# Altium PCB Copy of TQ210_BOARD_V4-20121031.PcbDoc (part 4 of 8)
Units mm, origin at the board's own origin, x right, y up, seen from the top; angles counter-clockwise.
Board outline 191.2 x 131.27 mm, 2 copper layers (TopLayer, BottomLayer); 362 components, 455 nets, 1594 pads, 630 vias.
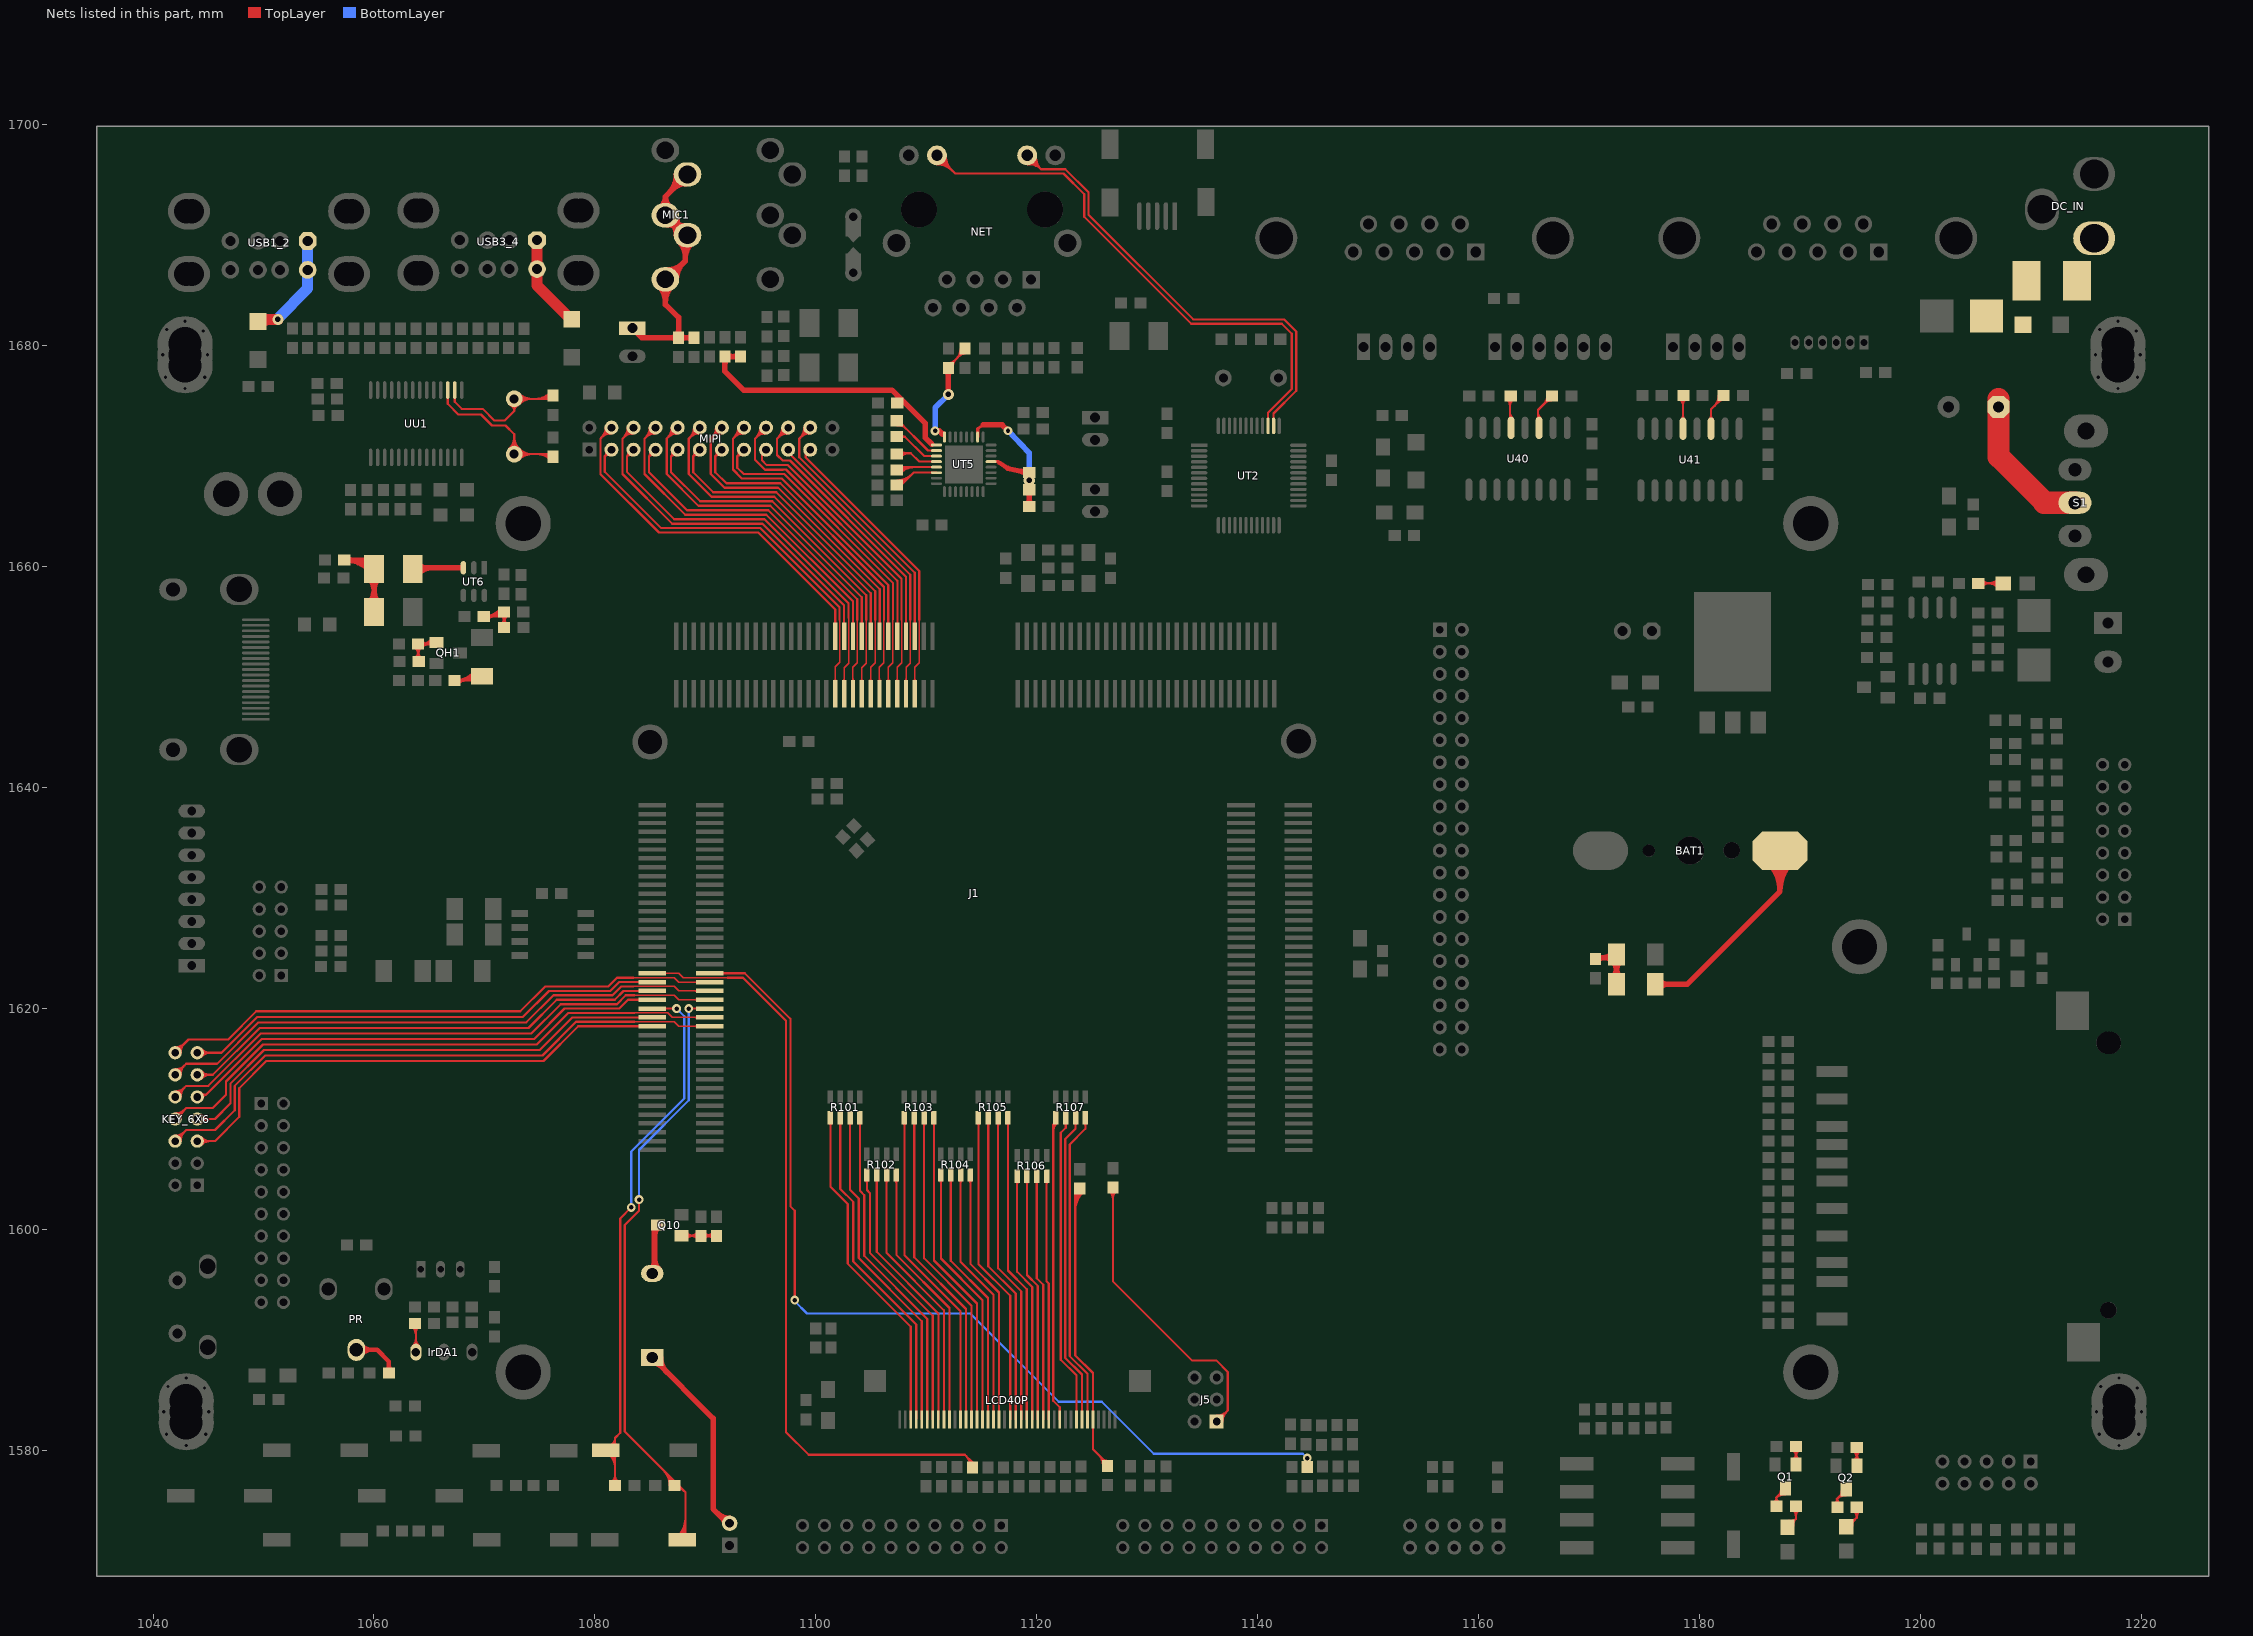
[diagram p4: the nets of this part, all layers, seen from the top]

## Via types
v1: diameter 1, hole 0.5, TopLayer to BottomLayer, 458 vias
v2: diameter 0.8, hole 0.4, TopLayer to BottomLayer, 172 vias

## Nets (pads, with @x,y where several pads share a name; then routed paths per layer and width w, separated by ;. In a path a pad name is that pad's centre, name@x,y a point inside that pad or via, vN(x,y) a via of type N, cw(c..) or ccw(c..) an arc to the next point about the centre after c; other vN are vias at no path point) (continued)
KP_COL2: J1.29 KEY_6X6.5 | length 50.1
  TopLayer w0.2: KEY_6X6.5@1044,1608 1045.6,1608 1047.8,1610.2 1047.8,1612.8 1050.25,1615.25 1075.35,1615.25 1078.5,1618.4 J1.29@1085.2,1618.4 ; KEY_6X6.5@1044.212,1607.788 cw(c1044.724,1607.276) 1044.724,1608 cw(c1044.724,1608.724) KEY_6X6.5@1044.212,1608.212 ; KEY_6X6.5@1044.354,1607.646 cw(c1045.207,1606.793) 1045.207,1608 cw(c1045.207,1609.207) KEY_6X6.5@1044.354,1608.354
KP_COL3: J1.30 KEY_6X6.6 | length 57.9
  TopLayer w0.135: 1083.6,1618.8 1087.2,1618.8 1087.6,1618.4 J1.30@1090.4,1618.4 ; J1.30@1089.256,1618.306 ccw(c1089.03,1618.08) 1089.03,1618.4 ccw(c1089.03,1618.72) J1.30@1089.256,1618.494
  TopLayer w0.2: KEY_6X6.6@1042,1608 1043,1609 1045.6,1609 1047.4,1610.8 1047.4,1613 1050.15,1615.75 1075.25,1615.75 1078.3,1618.8 1083.6,1618.8 ; KEY_6X6.6@1042,1608.3 ccw(c1042,1609.024) 1042.512,1608.512 ccw(c1043.024,1608) KEY_6X6.6@1042.3,1608 ; KEY_6X6.6@1042,1608.5 ccw(c1042,1609.707) 1042.854,1608.854 ccw(c1043.707,1608) KEY_6X6.6@1042.5,1608
KP_COL4: J1.31 KEY_6X6.7 | length 49.1
  TopLayer w0.2: KEY_6X6.7@1044,1610 1045.6,1610 1047,1611.4 1047,1613.2 1050.05,1616.25 1075,1616.25 1077.95,1619.2 J1.31@1085.2,1619.2 ; KEY_6X6.7@1044.212,1609.788 cw(c1044.724,1609.276) 1044.724,1610 cw(c1044.724,1610.724) KEY_6X6.7@1044.212,1610.212 ; KEY_6X6.7@1044.354,1609.646 cw(c1045.207,1608.793) 1045.207,1610 cw(c1045.207,1611.207) KEY_6X6.7@1044.354,1610.354
KP_COL5: J1.32 KEY_6X6.8 | length 56.8
  TopLayer w0.135: 1083.6,1619.6 1086.6,1619.6 1087,1619.2 J1.32@1090.4,1619.2 ; J1.32@1089.256,1619.106 ccw(c1089.03,1618.88) 1089.03,1619.2 ccw(c1089.03,1619.52) J1.32@1089.256,1619.294
  TopLayer w0.2: KEY_6X6.8@1042,1610 1043,1611 1045.4,1611 1046.6,1612.2 1046.6,1613.4 1049.95,1616.75 1074.75,1616.75 1077.6,1619.6 1083.6,1619.6 ; KEY_6X6.8@1042,1610.3 ccw(c1042,1611.024) 1042.512,1610.512 ccw(c1043.024,1610) KEY_6X6.8@1042.3,1610 ; KEY_6X6.8@1042,1610.5 ccw(c1042,1611.707) 1042.854,1610.854 ccw(c1043.707,1610) KEY_6X6.8@1042.5,1610
KP_COL6: J1.33 KEY7.1 R7.1 | length 55.3
  TopLayer w0.2: KEY7.1@1081.296,1579.646 cw(c1080.023,1578.373) 1081.824,1578.373 ; KEY7.1@1081.414,1580.441 ccw(c1081.05,1581.124) 1081.824,1581.124 ; KEY7.1@1081.438,1579.788 cw(c1080.506,1578.856) 1081.824,1578.856 ; KEY7.1@1081.509,1580.265 ccw(c1081.228,1580.79) 1081.824,1580.79 ; R7.1@1081.541,1577.107 ccw(c1080.858,1577.79) 1081.824,1577.79 ccw(c1082.79,1577.79) R7.1@1082.107,1577.107 ; KEY7.1@1081.579,1579.929 cw(c1080.988,1579.338) 1081.824,1579.338 ; R7.1@1081.824,1576.824 1081.824,1581.124 ; 1081.824,1579.213 cw(c1082.437,1579.213) KEY7.1@1082.004,1579.646 ; 1081.824,1580.787 ccw(c1082.437,1580.787) KEY7.1@1082.004,1580.354 ; v2(1083.3,1602) 1082.3,1601 1082.3,1581.6 1081.824,1581.124 ; J1.33@1085.21,1619.99 v2(1087.4,1620)
  BottomLayer w0.2: v2(1083.3,1602) 1083.3,1607.066 1088.1,1611.866 1088.1,1619.3 v2(1087.4,1620)
KP_COL7: J1.34 KEY8.1 R8.1 | length 63.4
  TopLayer w0.2: v2(1084,1602.7) 1084,1601.7 1082.7,1600.4 1082.7,1581.7 1088.2,1576.2 KEY8.1@1088.2,1571.9 ; 1086.207,1578.193 cw(c1084.838,1576.824) R8.1@1086.774,1576.824 ; 1086.548,1577.852 cw(c1085.521,1576.824) R8.1@1086.974,1576.824 ; 1086.89,1577.51 cw(c1086.204,1576.824) R8.1@1087.174,1576.824 ; R8.1@1087.274,1576.824 cw(c1087.328,1576.233) R8.1@1087.747,1576.653 ; R8.1@1087.292,1576.625 cw(c1087.378,1575.68) 1088.049,1576.351 ; KEY8.1@1087.546,1572.254 ccw(c1085.969,1573.831) 1088.2,1573.831 ; KEY8.1@1087.688,1572.112 ccw(c1086.451,1573.349) 1088.2,1573.349 ; KEY8.1@1087.829,1571.971 ccw(c1086.934,1572.866) 1088.2,1572.866 ; v2(1088.5,1620) J1.34@1090.41,1619.99
  BottomLayer w0.2: v2@1084,1602.9 1084,1607.2 1088.5,1611.7 v2(1088.5,1620)
KP_ROW0: J1.35 KEY_6X6.9 | length 46.3
  TopLayer w0.2: KEY_6X6.9@1043.8,1612 KEY_6X6.9@1044,1612 1044.2,1612.2 1044.8,1612.2 ; KEY_6X6.9@1044.297,1611.96 cw(c1044.571,1611.923) 1044.571,1612.2 ; KEY_6X6.9@1044.354,1612.354 ccw(c1044.724,1612.724) 1044.724,1612.2 ; KEY_6X6.9@1044.496,1611.934 cw(c1044.8,1611.893) 1044.8,1612.2 ; J1.35@1085.2,1620.8 1083.004,1620.8 1082.204,1620 1077.25,1620 1074.5,1617.25 1049.85,1617.25 1044.8,1612.2
KP_ROW1: J1.36 KEY_6X6.10 | length 55.9
  TopLayer w0.135: 1083.6,1621.2 1087.2,1621.2 1087.6,1620.8 J1.36@1090.4,1620.8 ; J1.36@1089.256,1620.706 ccw(c1089.03,1620.48) 1089.03,1620.8 ccw(c1089.03,1621.12) J1.36@1089.256,1620.894
  TopLayer w0.2: KEY_6X6.10@1042,1612 1043,1613 1045,1613 1049.75,1617.75 1074.25,1617.75 1076.9,1620.4 1082,1620.4 1082.8,1621.2 1083.6,1621.2 ; KEY_6X6.10@1042,1612.3 ccw(c1042,1613.024) 1042.512,1612.512 ccw(c1043.024,1612) KEY_6X6.10@1042.3,1612 ; KEY_6X6.10@1042,1612.5 ccw(c1042,1613.707) 1042.854,1612.854 ccw(c1043.707,1612) KEY_6X6.10@1042.5,1612
KP_ROW2: J1.37 KEY_6X6.11 | length 47.4
  TopLayer w0.2: KEY_6X6.11@1044,1614 1045.4,1614 1049.65,1618.25 1074,1618.25 1076.55,1620.8 1081.8,1620.8 1082.6,1621.6 J1.37@1085.2,1621.6 ; KEY_6X6.11@1044.212,1613.788 cw(c1044.724,1613.276) 1044.724,1614 cw(c1044.724,1614.724) KEY_6X6.11@1044.212,1614.212 ; KEY_6X6.11@1044.354,1613.646 cw(c1045.207,1612.793) 1045.207,1614 cw(c1045.207,1615.207) KEY_6X6.11@1044.354,1614.354
KP_ROW3: J1.38 KEY_6X6.12 | length 55.4
  TopLayer w0.135: 1083.5,1622 1087.2,1622 1087.6,1621.6 J1.38@1090.4,1621.6 ; J1.38@1089.256,1621.506 ccw(c1089.03,1621.28) 1089.03,1621.6 ccw(c1089.03,1621.92) J1.38@1089.256,1621.694
  TopLayer w0.2: KEY_6X6.12@1042,1614 1043,1615 1045.8,1615 1049.55,1618.75 1073.8,1618.75 1076.25,1621.2 1081.6,1621.2 1082.4,1622 1083.5,1622 ; KEY_6X6.12@1042,1614.3 ccw(c1042,1615.024) 1042.512,1614.512 ccw(c1043.024,1614) KEY_6X6.12@1042.3,1614 ; KEY_6X6.12@1042,1614.5 ccw(c1042,1615.707) 1042.854,1614.854 ccw(c1043.707,1614) KEY_6X6.12@1042.5,1614
KP_ROW4: J1.39 KEY_6X6.13 | length 46.9
  TopLayer w0.2: KEY_6X6.13@1044,1616 1046.2,1616 1049.45,1619.25 1073.5,1619.25 1075.85,1621.6 1081.4,1621.6 1082.2,1622.4 J1.39@1085.2,1622.4 ; KEY_6X6.13@1044.212,1615.788 cw(c1044.724,1615.276) 1044.724,1616 cw(c1044.724,1616.724) KEY_6X6.13@1044.212,1616.212 ; KEY_6X6.13@1044.354,1615.646 cw(c1045.207,1614.793) 1045.207,1616 cw(c1045.207,1617.207) KEY_6X6.13@1044.354,1616.354
KP_ROW5: J1.40 KEY_6X6.14 | length 54.4
  TopLayer w0.135: 1083.5,1622.8 1087.2,1622.8 1087.6,1622.4 J1.40@1090.4,1622.4
  TopLayer w0.2: KEY_6X6.14@1042,1616 1043.2,1617.2 1046.8,1617.2 1049.35,1619.75 1073.25,1619.75 1075.5,1622 1081.2,1622 1082,1622.8 1083.5,1622.8 ; KEY_6X6.14@1042,1616.3 ccw(c1042,1617.024) 1042.512,1616.512 ccw(c1043.024,1616) KEY_6X6.14@1042.3,1616 ; KEY_6X6.14@1042,1616.5 ccw(c1042,1617.707) 1042.854,1616.854 ccw(c1043.707,1616) KEY_6X6.14@1042.5,1616
KP_ROW6: J1.41 RM22.1 | length 71.4
  TopLayer w0.135: J1.41@1085.2,1623.2 1087.6,1623.2 1088,1622.8 1092,1622.8
  TopLayer w0.2: 1092,1622.8 1093.406,1622.8 1097.3,1618.906 1097.3,1581.654 1099.354,1579.6 1113.5,1579.6 1114.2,1578.9 RM22.1@1114.2,1578.448 ; 1113.621,1579.479 cw(c1112.704,1578.561) RM22.1@1114,1578.507 ; 1113.943,1579.157 cw(c1113.322,1578.535) RM22.1@1114.2,1578.498
KP_ROW7: J1.42 RMB22.1 | length 87
  TopLayer w0.2: J1.42@1090.41,1623.19 1090.421,1623.2 1093.572,1623.2 1097.7,1619.072 1097.7,1602.1 1098.1,1601.7 v2(1098.1,1593.6)
  BottomLayer w0.2: v2(1098.1,1593.6) 1098.1,1593.5 1099.2,1592.4 1114,1592.4 1122,1584.4 1125.9,1584.4 1130.6,1579.7 1144.1,1579.7 v2(1144.5,1579.3)
LAN2_LNK: NET.10 UT2.38 | length 46.2
  TopLayer w0.2: NET.10@1119.14,1697.25 1120.39,1696 ; NET.10@1119.179,1696.651 cw(c1119.254,1695.489) 1120.077,1696.313 cw(c1120.901,1697.136) NET.10@1119.739,1697.211 ; NET.10@1119.192,1696.452 cw(c1119.292,1694.902) 1120.39,1696 ; NET.10@1119.938,1697.198 ccw(c1121.488,1697.098) 1120.39,1696 ; UT2.38@1141.453,1672.754 1141.453,1673.888 1143.5,1675.934 1143.5,1681.3 1142.4,1682.4 1134.166,1682.4 1124.7,1691.866 1124.7,1693.9 1122.6,1696 1120.39,1696
LAN2_SPD: NET.11 UT2.39 | length 56.1
  TopLayer w0.2: NET.11@1110.97,1696.45 cw(c1110.97,1694.519) 1112.336,1695.884 cw(c1113.701,1697.25) NET.11@1111.77,1697.25 ; NET.11@1110.97,1696.65 cw(c1110.97,1695.201) 1111.994,1696.226 cw(c1113.019,1697.25) NET.11@1111.57,1697.25 ; NET.11@1110.97,1696.85 cw(c1110.97,1695.884) 1111.653,1696.567 cw(c1112.336,1697.25) NET.11@1111.37,1697.25 ; NET.11@1110.97,1697.25 1112.62,1695.6 1122.434,1695.6 1124.3,1693.734 1124.3,1691.7 1134,1682 1142.2,1682 1143.1,1681.1 1143.1,1676.1 1140.953,1673.953 UT2.39@1140.953,1672.754
LHSYNC: LCD40P.35 R107.8 | length 29.2
  TopLayer w0.2: R107.8@1124.305,1609.67 cw(c1124.049,1609.414) 1124.411,1609.414 cw(c1124.773,1609.414) R107.8@1124.517,1609.67 ; R107.8@1124.411,1610.126 1124.411,1609.111 1122.998,1607.698 1122.998,1588.534 1124.6,1586.931 LCD40P.35@1124.6,1582.7
LVCLK: CL5.1 LCD40P.36 R108.1 | length 34.2
  TopLayer w0.2: 1123.498,1601.713 cw(c1125.837,1601.713) R108.1@1124.183,1603.367 ; 1123.498,1602.196 cw(c1125.354,1602.196) R108.1@1124.041,1603.509 ; 1123.498,1602.679 cw(c1124.871,1602.679) R108.1@1123.9,1603.65 ; R108.1@1123.498,1603.162 cw(c1124.388,1603.162) R108.1@1123.759,1603.791 ; R108.1@1124.1,1604 1123.498,1603.398 1123.498,1588.599 1125.1,1586.997 LCD40P.36@1125.1,1582.8 1125.1,1580.1 CL5.1@1126.6,1578.6 ; 1125.611,1579.589 cw(c1124.672,1578.65) CL5.1@1126,1578.65 ; 1125.953,1579.247 cw(c1125.355,1578.65) CL5.1@1126.2,1578.65 ; 1125.973,1579.227 ccw(c1126.4,1579.654) CL5.1@1126.4,1579.05
LVD0: LCD40P.3 R101.5 | length 30.9
  TopLayer w0.2: R101.5@1101.227,1609.67 cw(c1100.971,1609.414) 1101.333,1609.414 cw(c1101.695,1609.414) R101.5@1101.439,1609.67 ; R101.5@1101.333,1610.126 1101.333,1603.857 1102.89,1602.3 1102.89,1596.91 1108.6,1591.2 LCD40P.3@1108.6,1582.8
LVD1: LCD40P.4 R101.6 | length 30.6
  TopLayer w0.2: R101.6@1102.116,1609.67 cw(c1101.86,1609.414) 1102.222,1609.414 cw(c1102.584,1609.414) R101.6@1102.328,1609.67 ; R101.6@1102.222,1610.126 1102.222,1603.668 1103.39,1602.5 1103.39,1597.11 1109.1,1591.4 LCD40P.4@1109.1,1582.9
LVD2: LCD40P.5 R101.7 | length 30.7
  TopLayer w0.2: R101.7@1103.005,1609.67 cw(c1102.775,1609.44) 1103.1,1609.44 ; 1103.1,1609.387 cw(c1103.5,1609.387) R101.7@1103.217,1609.67 ; R101.7@1103.1,1610.2 1103.1,1603.59 1103.89,1602.8 1103.89,1597.41 1109.6,1591.7 LCD40P.5@1109.6,1582.8
LVD3: LCD40P.6 R101.8 | length 30.4
  TopLayer w0.2: R101.8@1103.894,1609.67 cw(c1103.638,1609.414) 1104,1609.414 cw(c1104.362,1609.414) R101.8@1104.106,1609.67 ; R101.8@1104,1610.126 1104,1603.5 1104.39,1603.11 1104.39,1597.61 1110.1,1591.9 LCD40P.6@1110.1,1582.8
LVD4: LCD40P.7 R102.5 | length 25.2
  TopLayer w0.2: R102.5@1104.527,1604.47 cw(c1104.271,1604.214) 1104.633,1604.214 cw(c1104.995,1604.214) R102.5@1104.739,1604.47 ; R102.5@1104.633,1604.926 1104.633,1603.567 1104.9,1603.3 1104.9,1597.9 1110.6,1592.2 LCD40P.7@1110.6,1582.8
LVD5: LCD40P.8 R102.6 | length 25
  TopLayer w0.2: R102.6@1105.416,1604.47 cw(c1105.16,1604.214) 1105.522,1604.214 cw(c1105.884,1604.214) R102.6@1105.628,1604.47 ; R102.6@1105.522,1604.926 1105.522,1597.978 1111.1,1592.4 LCD40P.8@1111.1,1582.8
LVD6: LCD40P.9 R102.7 | length 24.9
  TopLayer w0.2: R102.7@1106.305,1604.47 cw(c1106.049,1604.214) 1106.411,1604.214 cw(c1106.773,1604.214) R102.7@1106.517,1604.47 ; R102.7@1106.411,1604.926 1106.411,1597.889 1111.6,1592.7 LCD40P.9@1111.6,1582.7
LVD7: LCD40P.10 R102.8 | length 24.7
  TopLayer w0.2: R102.8@1107.194,1604.47 cw(c1106.938,1604.214) 1107.3,1604.214 cw(c1107.662,1604.214) R102.8@1107.406,1604.47 ; R102.8@1107.3,1604.926 1107.3,1597.7 1112.1,1592.9 LCD40P.10@1112.1,1582.8
LVD8: LCD40P.12 R103.5 | length 30.1
  TopLayer w0.2: R103.5@1107.927,1609.67 cw(c1107.671,1609.414) 1108.033,1609.414 cw(c1108.395,1609.414) R103.5@1108.139,1609.67 ; R103.5@1108.033,1610.126 1108.033,1597.667 1113.1,1592.6 LCD40P.12@1113.1,1582.7
LVD9: LCD40P.13 R103.6 | length 29.8
  TopLayer w0.2: R103.6@1108.816,1609.67 cw(c1108.56,1609.414) 1108.922,1609.414 cw(c1109.284,1609.414) R103.6@1109.028,1609.67 ; R103.6@1108.922,1610.126 1108.922,1597.478 1113.6,1592.8 LCD40P.13@1113.6,1582.8
LVD10: LCD40P.14 R103.7 | length 29.7
  TopLayer w0.2: R103.7@1109.705,1609.67 cw(c1109.449,1609.414) 1109.811,1609.414 cw(c1110.173,1609.414) R103.7@1109.917,1609.67 ; R103.7@1109.811,1610.126 1109.811,1597.389 1114.1,1593.1 LCD40P.14@1114.1,1582.8
LVD11: LCD40P.15 R103.8 | length 29.5
  TopLayer w0.2: R103.8@1110.594,1609.67 cw(c1110.338,1609.414) 1110.7,1609.414 cw(c1111.062,1609.414) R103.8@1110.806,1609.67 ; R103.8@1110.7,1610.126 1110.7,1597.2 1114.6,1593.3 LCD40P.15@1114.6,1582.8
LVD12: LCD40P.16 R104.5 | length 24.3
  TopLayer w0.2: R104.5@1111.227,1604.47 cw(c1110.971,1604.214) 1111.333,1604.214 cw(c1111.695,1604.214) R104.5@1111.439,1604.47 ; R104.5@1111.333,1604.926 1111.333,1597.367 1115.1,1593.6 LCD40P.16@1115.1,1582.8
LVD13: LCD40P.17 R104.6 | length 24
  TopLayer w0.2: R104.6@1112.116,1604.47 cw(c1111.86,1604.214) 1112.222,1604.214 cw(c1112.584,1604.214) R104.6@1112.328,1604.47 ; R104.6@1112.222,1604.926 1112.222,1597.178 1115.6,1593.8 LCD40P.17@1115.6,1582.9
LVD14: LCD40P.18 R104.7 | length 23.8
  TopLayer w0.2: R104.7@1113.005,1604.47 cw(c1112.749,1604.214) 1113.111,1604.214 cw(c1113.473,1604.214) R104.7@1113.217,1604.47 ; R104.7@1113.111,1604.926 1113.111,1597.089 1116.1,1594.1 LCD40P.18@1116.1,1582.9
LVD15: LCD40P.19 R104.8 | length 23.8
  TopLayer w0.2: R104.8@1113.894,1604.47 cw(c1113.638,1604.214) 1114,1604.214 cw(c1114.362,1604.214) R104.8@1114.106,1604.47 ; R104.8@1114,1604.926 1114,1596.9 1116.6,1594.3 LCD40P.19@1116.6,1582.8
LVD16: LCD40P.21 R105.5 | length 29.1
  TopLayer w0.2: R105.5@1114.627,1609.67 cw(c1114.371,1609.414) 1114.733,1609.414 cw(c1115.095,1609.414) R105.5@1114.839,1609.67 ; R105.5@1114.733,1610.126 1114.733,1596.862 1117.6,1593.995 LCD40P.21@1117.6,1582.8
LVD17: LCD40P.22 R105.6 | length 28.9
  TopLayer w0.2: R105.6@1115.516,1609.67 cw(c1115.26,1609.414) 1115.622,1609.414 cw(c1115.984,1609.414) R105.6@1115.728,1609.67 ; R105.6@1115.622,1610.126 1115.622,1596.673 1118.1,1594.195 LCD40P.22@1118.1,1582.8
LVD18: LCD40P.23 R105.7 | length 28.8
  TopLayer w0.2: R105.7@1116.405,1609.67 cw(c1116.149,1609.414) 1116.511,1609.414 cw(c1116.873,1609.414) R105.7@1116.617,1609.67 ; R105.7@1116.511,1610.126 1116.511,1596.484 1118.6,1594.395 LCD40P.23@1118.6,1582.8
LVD19: LCD40P.24 R105.8 | length 28.6
  TopLayer w0.2: R105.8@1117.294,1609.67 cw(c1117.038,1609.414) 1117.4,1609.414 cw(c1117.762,1609.414) R105.8@1117.506,1609.67 ; R105.8@1117.4,1610.126 1117.4,1596.295 1119.1,1594.595 LCD40P.24@1119.1,1582.8
LVD20: LCD40P.25 R106.5 | length 23.2
  TopLayer w0.2: R106.5@1118.127,1604.37 cw(c1117.871,1604.114) 1118.233,1604.114 cw(c1118.595,1604.114) R106.5@1118.339,1604.37 ; R106.5@1118.233,1604.826 1118.233,1596.162 1119.6,1594.795 LCD40P.25@1119.6,1582.8
LVD21: LCD40P.26 R106.6 | length 23
  TopLayer w0.2: R106.6@1119.016,1604.37 cw(c1118.76,1604.114) 1119.122,1604.114 cw(c1119.484,1604.114) R106.6@1119.228,1604.37 ; R106.6@1119.122,1604.826 1119.122,1595.873 1120.1,1594.895 LCD40P.26@1120.1,1582.8
LVD22: LCD40P.27 R106.7 | length 22.8
  TopLayer w0.2: R106.7@1119.905,1604.37 cw(c1119.649,1604.114) 1120.011,1604.114 cw(c1120.373,1604.114) R106.7@1120.117,1604.37 ; R106.7@1120.011,1604.826 1120.011,1595.589 1120.6,1595 LCD40P.27@1120.6,1582.8
LVD23: LCD40P.28 R106.8 | length 22.7
  TopLayer w0.2: R106.8@1120.794,1604.37 cw(c1120.538,1604.114) 1120.9,1604.114 cw(c1121.262,1604.114) R106.8@1121.006,1604.37 ; R106.8@1120.9,1604.826 1120.9,1595.3 1121.1,1595.1 LCD40P.28@1121.1,1582.8
LVDEN: LCD40P.33 R107.6 | length 28.8
  TopLayer w0.2: R107.6@1122.527,1609.67 cw(c1122.271,1609.414) 1122.633,1609.414 cw(c1122.995,1609.414) R107.6@1122.739,1609.67 ; R107.6@1122.633,1610.126 1122.633,1609.2 1122.19,1608.757 1122.19,1588.21 1123.6,1586.8 LCD40P.33@1123.6,1582.7
LVSYNC: LCD40P.34 R107.7 | length 28.9
  TopLayer w0.2: R107.7@1123.416,1609.67 cw(c1123.16,1609.414) 1123.522,1609.414 cw(c1123.884,1609.414) R107.7@1123.628,1609.67 ; R107.7@1123.522,1610.126 1123.522,1609.122 1122.598,1608.198 1122.598,1588.368 1124.1,1586.866 LCD40P.34@1124.1,1582.8
LXPWMTOUT0: LCD40P.30 R107.5 | length 29.7
  TopLayer w0.2: 1121.5,1608.825 cw(c1122.695,1608.825) R107.5@1121.85,1609.67 ; 1121.5,1609.308 cw(c1122.212,1609.308) R107.5@1121.709,1609.811 ; 1121.516,1609.516 ccw(c1121.317,1609.715) R107.5@1121.596,1609.755 ; R107.5@1121.543,1609.543 cw(c1121.744,1609.341) R107.5@1121.744,1609.626 ; R107.5@1121.744,1610.126 1121.744,1609.744 1121.5,1609.5 1121.5,1584.5 1122.1,1583.9 LCD40P.30@1122.1,1582.8
LXPWMTOUT3: J5.1 R109.1 | length 35.3
  TopLayer w0.2: R109.1@1126.617,1603.467 cw(c1125.934,1602.784) 1126.9,1602.784 cw(c1127.866,1602.784) R109.1@1127.183,1603.467 ; R109.1@1126.9,1603.8 1126.9,1595.3 1134.052,1588.148 1136.252,1588.148 1137.3,1587.1 1137.3,1583.6 J5.1@1136.3,1582.6 ; J5.1@1136.872,1583.172 cw(c1136.3,1583.744) 1136.3,1582.935 ccw(c1136.3,1583.744) J5.1@1136.872,1583.172 ; J5.1@1136.872,1583.172 ccw(c1137.444,1582.6) 1136.635,1582.6 cw(c1137.444,1582.6) J5.1@1136.872,1583.172 ; 1137.213,1583.513 cw(c1136.3,1584.427) 1136.3,1583.135 ccw(c1136.3,1584.427) 1137.213,1583.513 ; 1137.213,1583.513 ccw(c1138.127,1582.6) 1136.835,1582.6 cw(c1138.127,1582.6) 1137.213,1583.513
MIC: C524.1 UT5.4 | length 6
  TopLayer w0.2: C524.1@1107.329,1670.278 1108.603,1670.278 1109.357,1669.524 UT5.4@1110.928,1669.524 ; C524.1@1107.519,1670.083 cw(c1107.992,1669.61) 1107.992,1670.278 ; C524.1@1107.661,1669.941 cw(c1108.475,1669.127) 1108.475,1670.278 ; C524.1@1107.661,1670.507 ccw(c1108.212,1671.058) 1108.212,1670.278
MIC1_P1: C525.1 MIC1.2 MIC1.3 MIC1.10 MIC1.11 MIC2.1 R505.1 | length 51.5
  TopLayer w0.5: MIC2.1@1083.4,1681.6 1084.264,1680.736 1088.979,1680.736 R505.1@1088.981,1680.733 ; MIC1.10@1085.784,1685.424 cw(c1084.333,1683.973) 1086.385,1683.973 cw(c1088.437,1683.973) MIC1.10@1086.986,1685.424 ; MIC1.11@1085.875,1692.505 ccw(c1085.11,1693.525) 1086.385,1693.525 ; MIC1.10@1086.285,1685.775 1088.185,1687.675 MIC1.3@1088.185,1690.025 ; 1086.385,1683.707 MIC1.10@1086.385,1686.025 ; 1086.385,1683.766 1087.574,1682.577 C525.1@1087.574,1680.736 ; MIC1.10@1086.535,1686.875 ccw(c1086.535,1688.927) 1087.986,1687.476 ccw(c1089.437,1686.025) MIC1.10@1087.385,1686.025 ; MIC1.11@1086.535,1690.975 cw(c1086.535,1689.285) MIC1.3@1087.73,1690.48 ; 1086.678,1693.818 ccw(c1084.971,1695.525) MIC1.2@1087.385,1695.525 ; MIC1.11@1086.699,1691.511 ccw(c1088.235,1693.047) MIC1.3@1088.235,1690.875 ; MIC1.11@1086.82,1691.39 cw(c1085.454,1690.025) MIC1.3@1087.385,1690.025 ; MIC1.11@1086.885,1691.825 ccw(c1088.092,1691.825) 1087.239,1690.971 ; MIC1.11@1086.895,1692.505 cw(c1087.66,1693.525) 1086.385,1693.525 ; 1087.04,1694.18 cw(c1088.235,1692.985) MIC1.2@1088.235,1694.675 ; MIC1.11@1087.385,1691.825 ccw(c1089.799,1691.825) MIC1.3@1088.092,1690.118 ; C525.1@1087.397,1680.559 ccw(c1086.97,1680.132) 1086.97,1680.736 ccw(c1086.97,1681.339) C525.1@1087.397,1680.912 ; C525.1@1087.397,1680.962 ccw(c1086.97,1681.389) 1087.574,1681.389 ccw(c1088.178,1681.389) C525.1@1087.751,1680.962 ; 1087.532,1694.671 ccw(c1086.678,1695.525) MIC1.2@1087.885,1695.525 ; MIC1.3@1087.634,1689.424 cw(c1086.304,1688.093) 1088.185,1688.093 ; C525.1@1087.751,1680.559 cw(c1088.178,1680.132) 1088.178,1680.736 cw(c1088.178,1681.339) C525.1@1087.751,1680.912 ; 1088.185,1687.852 cw(c1090.408,1687.852) MIC1.3@1088.836,1689.424 ; 1088.372,1680.736 cw(c1088.372,1680.125) R505.1@1088.804,1680.557 ; 1088.383,1680.736 ccw(c1088.383,1681.332) R505.1@1088.804,1680.91 ; MIC1.3@1088.385,1690.025 MIC1.3@1088.185,1690.025 ; MIC1.2@1088.385,1695.525 1086.385,1693.525 ; R505.1@1088.97,1680.83 R505.1@1089,1680.8 ; 1086.385,1693.525 MIC1.11@1086.385,1691.825 MIC1.3@1088.185,1690.025
MICBIAS: C509.1 C511.1 R504.2 UT5.1 | length 29.5
  TopLayer w0.5: C509.1@1091.604,1678.807 cw(c1091.177,1678.38) 1091.781,1678.38 cw(c1092.385,1678.38) C509.1@1091.958,1678.807 ; C509.1@1091.958,1678.857 cw(c1092.385,1678.43) 1092.385,1679.033 cw(c1092.385,1679.637) C509.1@1091.958,1679.21 ; C511.1@1093.004,1678.857 ccw(c1092.577,1678.43) 1092.577,1679.033 ccw(c1092.577,1679.637) C511.1@1093.004,1679.21 ; C511.1@1093.181,1679.033 C509.1@1091.781,1679.033 1091.781,1677.683 1093.464,1676 1106.9,1676 1109.9,1673 1109.9,1671.7 UT5.1@1110.501,1671.099 ; 1107.281,1675.619 cw(c1106.556,1674.894) R504.2@1107.577,1674.801 ; R504.2@1107.428,1675.074 cw(c1107.428,1674.113) 1108.108,1674.792
MIPI_MD_DN0: J1.128 MIPI.13 | length 33.3
  TopLayer w0.135: J1.128@1105.677,1649.649 ccw(c1105.451,1649.876) 1105.771,1649.876 ccw(c1106.09,1649.876) J1.128@1105.864,1649.649 ; J1.128@1105.771,1648.506 1105.771,1650.905 1106.17,1651.305 1106.17,1655.394
  TopLayer w0.2: MIPI.13@1090.996,1670.422 cw(c1090.613,1670.287) 1090.9,1670 ; MIPI.13@1091.322,1670.096 ccw(c1091.187,1669.713) 1090.9,1670 ; MIPI.13@1091.5,1670.6 1090.9,1670 ; 1106.17,1655.191 1106.17,1658.163 1096.778,1667.554 1091.911,1667.554 1090.9,1668.566 1090.9,1670
MIPI_MD_DN1: J1.130 MIPI.15 | length 32.1
  TopLayer w0.135: J1.130@1106.477,1649.649 ccw(c1106.251,1649.876) 1106.571,1649.876 ccw(c1106.89,1649.876) J1.130@1106.664,1649.649 ; J1.130@1106.571,1648.506 1106.571,1650.893 1106.983,1651.305 1106.983,1655.394
  TopLayer w0.2: MIPI.15@1092.996,1670.422 cw(c1092.613,1670.287) 1092.9,1670 ; MIPI.15@1093.322,1670.096 ccw(c1093.187,1669.713) 1092.9,1670 ; MIPI.15@1093.5,1670.6 1092.9,1670 ; 1106.983,1655.216 1106.983,1658.544 1097.134,1668.393 1093.473,1668.393 1092.9,1668.966 1092.9,1670
MIPI_MD_DN2: J1.132 MIPI.17 | length 29.5
  TopLayer w0.135: J1.132@1107.277,1649.649 ccw(c1107.051,1649.876) 1107.371,1649.876 ccw(c1107.69,1649.876) J1.132@1107.464,1649.649 ; J1.132@1107.371,1648.506 1107.371,1650.905 1107.77,1651.305 1107.77,1655.394
  TopLayer w0.2: MIPI.17@1095.5,1670.6 1095.132,1670.232 1095.132,1669.633 1095.56,1669.205 1097.49,1669.205 1107.77,1658.925 1107.77,1655.191
MIPI_MD_DN3: J1.134 MIPI.19 | length 27.2
  TopLayer w0.135: J1.134@1108.077,1649.649 ccw(c1107.851,1649.876) 1108.171,1649.876 ccw(c1108.49,1649.876) J1.134@1108.264,1649.649 ; J1.134@1108.171,1648.506 1108.171,1650.892 1108.558,1651.279 1108.558,1655.394
  TopLayer w0.2: MIPI.19@1097.585,1670.253 1097.592,1670.253 1108.558,1659.287 1108.558,1655.191
MIPI_MD_DP0: J1.127 MIPI.14 | length 31.8
  TopLayer w0.2: MIPI.14@1090.965,1672.6 cw(c1089.673,1672.6) 1090.587,1671.687 cw(c1091.5,1670.773) MIPI.14@1091.5,1672.065 ; MIPI.14@1091.165,1672.6 cw(c1090.356,1672.6) 1090.928,1672.028 cw(c1091.5,1671.456) MIPI.14@1091.5,1672.265 ; MIPI.14@1091.5,1672.6 1090.5,1671.6 1090.5,1668.4 1091.746,1667.154 1096.594,1667.154 1105.789,1657.96 1105.789,1653.724 J1.127@1105.771,1653.706
MIPI_MD_DP1: J1.129 MIPI.16 | length 30.6
  TopLayer w0.2: MIPI.16@1092.965,1672.6 cw(c1091.673,1672.6) 1092.587,1671.687 cw(c1093.5,1670.773) MIPI.16@1093.5,1672.065 ; MIPI.16@1093.165,1672.6 cw(c1092.356,1672.6) 1092.928,1672.028 cw(c1093.5,1671.456) MIPI.16@1093.5,1672.265 ; MIPI.16@1093.5,1672.6 1092.5,1671.6 1092.5,1668.8 1093.307,1667.993 1096.924,1667.993 1106.571,1658.346 J1.129@1106.571,1653.706
MIPI_MD_DP2: J1.131 MIPI.18 | length 30.1
  TopLayer w0.2: MIPI.18@1094.965,1672.6 cw(c1093.673,1672.6) 1094.587,1671.687 cw(c1095.5,1670.773) MIPI.18@1095.5,1672.065 ; MIPI.18@1095.165,1672.6 cw(c1094.356,1672.6) 1094.928,1672.028 cw(c1095.5,1671.456) MIPI.18@1095.5,1672.265 ; MIPI.18@1095.5,1672.6 1094.5,1671.6 1094.5,1669.7 1095.407,1668.793 1097.007,1668.793 ; 1095.985,1668.805 1097.305,1668.805 1107.37,1658.741 ; J1.131@1107.371,1653.706 1107.389,1653.724 1107.389,1658.722
MIPI_MD_DP3: J1.133 MIPI.20 | length 27.8
  TopLayer w0.2: MIPI.20@1096.965,1672.6 cw(c1095.673,1672.6) 1096.587,1671.687 cw(c1097.5,1670.773) MIPI.20@1097.5,1672.065 ; MIPI.20@1097.165,1672.6 cw(c1096.356,1672.6) 1096.928,1672.028 cw(c1097.5,1671.456) MIPI.20@1097.5,1672.265 ; MIPI.20@1097.5,1672.6 1096.5,1671.6 1096.5,1670.118 1097,1669.618 1097.661,1669.618 1108.171,1659.109 J1.133@1108.171,1653.706
MIPI_MD_NCLK: J1.136 MIPI.21 | length 27.4
  TopLayer w0.135: J1.136@1108.877,1649.649 ccw(c1108.651,1649.876) 1108.971,1649.876 ccw(c1109.29,1649.876) J1.136@1109.064,1649.649 ; J1.136@1108.971,1648.506 1108.971,1650.905 1109.37,1651.305 1109.37,1655.394
  TopLayer w0.2: MIPI.21@1099.5,1670.6 1099.094,1670.194 1099.094,1669.894 1109.37,1659.617 1109.37,1655.191
MIPI_MD_PCLK: J1.135 MIPI.22 | length 26.9
  TopLayer w0.2: MIPI.22@1098.965,1672.6 cw(c1097.673,1672.6) 1098.587,1671.687 cw(c1099.5,1670.773) MIPI.22@1099.5,1672.065 ; MIPI.22@1099.165,1672.6 cw(c1098.356,1672.6) 1098.928,1672.028 cw(c1099.5,1671.456) MIPI.22@1099.5,1672.265 ; MIPI.22@1099.5,1672.6 1098.5,1671.6 1098.5,1669.922 1108.971,1659.452 J1.135@1108.971,1653.706
MIPI_SD_DN0: J1.118 MIPI.3 | length 38.2
  TopLayer w0.135: J1.118@1101.671,1649.641 ccw(c1101.445,1649.867) 1101.765,1649.867 ccw(c1102.084,1649.867) J1.118@1101.858,1649.641 ; J1.118@1101.765,1648.497 1101.765,1650.963 1102.157,1651.356 1102.157,1655.394
  TopLayer w0.2: MIPI.3@1080.996,1670.422 cw(c1080.613,1670.287) 1080.9,1670 ; MIPI.3@1081.322,1670.096 ccw(c1081.187,1669.713) 1080.9,1670 ; MIPI.3@1081.5,1670.6 1080.9,1670 ; 1102.157,1655.191 1102.157,1656.334 1094.991,1663.5 1086,1663.5 1080.9,1668.6 1080.9,1670
MIPI_SD_DN1: J1.120 MIPI.5 | length 37
  TopLayer w0.135: J1.120@1102.471,1649.641 ccw(c1102.245,1649.867) 1102.565,1649.867 ccw(c1102.884,1649.867) J1.120@1102.658,1649.641 ; J1.120@1102.565,1648.497 1102.565,1650.865 1102.97,1651.27 1102.97,1655.394
  TopLayer w0.2: MIPI.5@1082.996,1670.422 cw(c1082.613,1670.287) 1082.9,1670 ; MIPI.5@1083.322,1670.096 ccw(c1083.187,1669.713) 1082.9,1670 ; MIPI.5@1083.5,1670.6 1082.9,1670 ; 1102.97,1655.394 1102.97,1656.69 1095.356,1664.303 1087.197,1664.303 1082.9,1668.6 1082.9,1670
MIPI_SD_DN2: J1.122 MIPI.7 | length 36.2
  TopLayer w0.135: J1.122@1103.277,1649.649 ccw(c1103.051,1649.876) 1103.371,1649.876 ccw(c1103.69,1649.876) J1.122@1103.464,1649.649 ; J1.122@1103.371,1648.506 1103.371,1650.918 1103.757,1651.305 1103.757,1655.394
  TopLayer w0.2: MIPI.7@1084.996,1670.422 cw(c1084.613,1670.287) 1084.9,1670 ; MIPI.7@1085.322,1670.096 ccw(c1085.187,1669.713) 1084.9,1670 ; MIPI.7@1085.5,1670.6 1084.9,1670 ; 1103.757,1655.191 1103.757,1657.071 1095.712,1665.116 1088.35,1665.116 1084.9,1668.566 1084.9,1670
MIPI_SD_DN3: J1.124 MIPI.9 | length 35.3
  TopLayer w0.135: J1.124@1104.077,1649.649 ccw(c1103.851,1649.876) 1104.171,1649.876 ccw(c1104.49,1649.876) J1.124@1104.264,1649.649 ; J1.124@1104.171,1648.506 1104.171,1650.88 1104.57,1651.279 1104.57,1655.394
  TopLayer w0.2: MIPI.9@1086.996,1670.422 cw(c1086.613,1670.287) 1086.9,1670 ; MIPI.9@1087.322,1670.096 ccw(c1087.187,1669.713) 1086.9,1670 ; MIPI.9@1087.5,1670.6 1086.9,1670 ; 1104.57,1655.191 1104.57,1657.426 1096.067,1665.929 1089.537,1665.929 1086.9,1668.566 1086.9,1670
MIPI_SD_DP0: J1.117 MIPI.4 | length 36.7
  TopLayer w0.2: MIPI.4@1080.965,1672.6 cw(c1079.673,1672.6) 1080.587,1671.687 cw(c1081.5,1670.773) MIPI.4@1081.5,1672.065 ; MIPI.4@1081.165,1672.6 cw(c1080.356,1672.6) 1080.928,1672.028 cw(c1081.5,1671.456) MIPI.4@1081.5,1672.265 ; MIPI.4@1081.5,1672.6 1080.5,1671.6 1080.5,1668.4 1085.8,1663.1 1094.8,1663.1 1101.765,1656.135 J1.117@1101.765,1653.697
MIPI_SD_DP1: J1.119 MIPI.6 | length 35.7
  TopLayer w0.2: MIPI.6@1082.965,1672.6 cw(c1081.673,1672.6) 1082.587,1671.687 cw(c1083.5,1670.773) MIPI.6@1083.5,1672.065 ; MIPI.6@1083.165,1672.6 cw(c1082.356,1672.6) 1082.928,1672.028 cw(c1083.5,1671.456) MIPI.6@1083.5,1672.265 ; MIPI.6@1083.5,1672.6 1082.5,1671.6 1082.5,1668.4 1086.997,1663.903 1095.172,1663.903 1102.565,1656.51 J1.119@1102.565,1653.697
MIPI_SD_DP2: J1.121 MIPI.8 | length 34.7
  TopLayer w0.2: MIPI.8@1084.965,1672.6 cw(c1083.673,1672.6) 1084.587,1671.687 cw(c1085.5,1670.773) MIPI.8@1085.5,1672.065 ; MIPI.8@1085.165,1672.6 cw(c1084.356,1672.6) 1084.928,1672.028 cw(c1085.5,1671.456) MIPI.8@1085.5,1672.265 ; MIPI.8@1085.5,1672.6 1084.5,1671.6 1084.5,1668.4 1088.184,1664.716 1095.527,1664.716 1103.371,1656.873 J1.121@1103.371,1653.706
MIPI_SD_DP3: J1.123 MIPI.10 | length 33.7
  TopLayer w0.2: MIPI.10@1086.965,1672.6 cw(c1085.673,1672.6) 1086.587,1671.687 cw(c1087.5,1670.773) MIPI.10@1087.5,1672.065 ; MIPI.10@1087.165,1672.6 cw(c1086.356,1672.6) 1086.928,1672.028 cw(c1087.5,1671.456) MIPI.10@1087.5,1672.265 ; MIPI.10@1087.5,1672.6 1086.5,1671.6 1086.5,1668.4 1089.371,1665.529 1095.883,1665.529 1104.171,1657.241 J1.123@1104.171,1653.706
MIPI_SD_NCLK: J1.126 MIPI.11 | length 34.3
  TopLayer w0.135: J1.126@1104.877,1649.649 ccw(c1104.651,1649.876) 1104.971,1649.876 ccw(c1105.29,1649.876) J1.126@1105.064,1649.649 ; J1.126@1104.971,1648.506 1104.971,1650.893 1105.383,1651.305 1105.383,1655.394
  TopLayer w0.2: MIPI.11@1088.996,1670.422 cw(c1088.613,1670.287) 1088.9,1670 ; MIPI.11@1089.322,1670.096 ccw(c1089.187,1669.713) 1088.9,1670 ; MIPI.11@1089.5,1670.6 1088.9,1670 ; 1105.383,1655.191 1105.383,1657.782 1096.423,1666.742 1090.724,1666.742 1088.9,1668.566 1088.9,1670
MIPI_SD_PCLK: J1.125 MIPI.12 | length 32.8
  TopLayer w0.2: MIPI.12@1088.965,1672.6 cw(c1087.673,1672.6) 1088.587,1671.687 cw(c1089.5,1670.773) MIPI.12@1089.5,1672.065 ; MIPI.12@1089.165,1672.6 cw(c1088.356,1672.6) 1088.928,1672.028 cw(c1089.5,1671.456) MIPI.12@1089.5,1672.265 ; MIPI.12@1089.5,1672.6 1088.5,1671.6 1088.5,1668.4 1090.558,1666.342 1096.239,1666.342 1104.971,1657.61 J1.125@1104.971,1653.706
NetBAT1_1: BAT1.1 D4.1 | length 29.9
  TopLayer w0.5: D4.1@1176,1622.2 1178.9,1622.2 1187.3,1630.6 BAT1.1@1187.3,1634.3 ; D4.1@1176.354,1621.846 cw(c1177.207,1620.993) 1177.207,1622.2 cw(c1177.207,1623.407) D4.1@1176.354,1622.554 ; BAT1.1@1186.239,1633.239 cw(c1183.679,1630.679) 1187.3,1630.679 cw(c1190.921,1630.679) BAT1.1@1188.361,1633.239 ; BAT1.1@1186.593,1633.593 cw(c1184.886,1631.886) 1187.3,1631.886 cw(c1189.714,1631.886) BAT1.1@1188.007,1633.593
NetC401_1: C401.1 U40.3 | length 6.2
  TopLayer w0.2: U40.3@1165.388,1672.481 1165.388,1674.2 C401.1@1166.669,1675.48 ; 1165.388,1674.024 ccw(c1166.224,1674.024) U40.3@1165.633,1673.433 ; 1165.901,1674.712 ccw(c1165.133,1675.48) C401.1@1166.219,1675.48 ; 1166.022,1674.833 cw(c1166.619,1674.235) C401.1@1166.619,1675.08 ; C401.1@1166.242,1675.054 ccw(c1165.816,1675.48) C401.1@1166.419,1675.48
NetC402_2: C402.2 U40.5 | length 5.6
  TopLayer w0.2: C402.2@1162.586,1675.198 cw(c1161.954,1674.565) 1162.848,1674.565 ; U40.5@1162.848,1672.481 1162.848,1675.41 C402.2@1162.919,1675.48 ; 1162.848,1674.024 ccw(c1163.684,1674.024) U40.5@1163.093,1673.433 ; 1162.848,1674.464 cw(c1163.885,1674.464) C402.2@1163.152,1675.198 ; 1162.848,1674.947 cw(c1163.402,1674.947) C402.2@1163.011,1675.339
NetC411_1: C411.1 U41.3 | length 6.1
  TopLayer w0.2: U41.3@1180.915,1673.356 ccw(c1180.566,1673.706) 1181.06,1673.706 ccw(c1181.554,1673.706) U41.3@1181.205,1673.356 ; U41.3@1181.06,1672.7 1181.06,1674.26 C411.1@1182.2,1675.4 ; 1181.361,1674.561 ccw(c1180.422,1675.5) C411.1@1181.75,1675.5 ; 1181.703,1674.903 ccw(c1181.105,1675.5) C411.1@1181.95,1675.5 ; 1181.723,1674.923 cw(c1182.15,1674.496) C411.1@1182.15,1675.1
NetC412_2: C412.2 U41.5 | length 5.6
  TopLayer w0.2: C412.2@1178.217,1675.217 cw(c1177.486,1674.486) 1178.52,1674.486 ; C412.2@1178.35,1675.5 1178.52,1675.33 U41.5@1178.52,1672.7 ; C412.2@1178.359,1675.359 cw(c1177.969,1674.969) 1178.52,1674.969 ; U41.5@1178.375,1673.356 ccw(c1178.026,1673.706) 1178.52,1673.706 ccw(c1179.014,1673.706) U41.5@1178.665,1673.356 ; 1178.52,1674.583 cw(c1179.417,1674.583) C412.2@1178.783,1675.217
NetC503_1: C503.1 UT5.6 | length 7.4
  TopLayer w0.2: C503.1@1107.328,1667.424 1107.758,1667.424 1108.858,1668.524 UT5.6@1110.928,1668.524 ; C503.1@1107.378,1667.424 ccw(c1107.378,1668.342) 1108.027,1667.693 ; C503.1@1107.378,1667.624 ccw(c1107.378,1669.025) 1108.368,1668.034 ; C503.1@1107.378,1667.824 ccw(c1107.378,1669.708) 1108.71,1668.376
NetC504_1: C504.1 UT5.5 | length 6.5
  TopLayer w0.2: C504.1@1107.379,1668.778 cw(c1107.972,1668.185) 1107.972,1669.024 ; C504.1@1107.52,1668.637 cw(c1108.454,1667.703) 1108.454,1669.024 ; C504.1@1107.576,1669.02 1107.58,1669.024 UT5.5@1110.928,1669.024 ; C504.1@1107.661,1668.496 cw(c1108.937,1667.22) 1108.937,1669.024
NetC505_1: C505.1 UT5.3 | length 5.2
  TopLayer w0.2: C505.1@1107.329,1671.778 1108.068,1671.778 ; C505.1@1107.726,1671.58 cw(c1108.068,1671.384) 1108.068,1671.778 ; C505.1@1107.726,1671.977 ccw(c1108.068,1672.172) 1108.068,1671.778 ; UT5.3@1110.928,1670.024 1109.822,1670.024 1108.068,1671.778
NetC513_1: C513.1 L506.1 L507.1 UT5.21 UT5.26 | length 20.5
  TopLayer w0.25: UT5.21@1115.878,1669.524 1116.52,1669.524
  TopLayer w0.3: UT5.26@1114.653,1671.749 1114.653,1672.49 1115.17,1672.855
  TopLayer w0.4: 1116.628,1669.424 1117.4,1668.9
  TopLayer w0.5: 1115.17,1672.855 1116.872,1672.855 v2(1117.405,1672.322) ; 1117.4,1668.9 C513.1@1119.2,1668.5 ; 1118.585,1668.637 ccw(c1118.746,1669.36) C513.1@1119.144,1668.735 ; 1118.775,1668.594 cw(c1118.674,1668.14) C513.1@1119.067,1668.39 ; L507.1@1119.151,1665.653 ccw(c1118.724,1666.08) 1119.328,1666.08 ccw(c1119.931,1666.08) L507.1@1119.505,1665.653 ; L506.1@1119.151,1666.799 cw(c1118.724,1666.372) 1119.328,1666.372 cw(c1119.931,1666.372) L506.1@1119.505,1666.799 ; L506.1@1119.151,1667.153 ccw(c1118.724,1667.58) 1119.328,1667.58 ccw(c1119.931,1667.58) L506.1@1119.505,1667.153 ; L507.1@1119.328,1665.524 v1(1119.328,1667.824) ; v1@1119.328,1667.92 cw(c1119.931,1667.92) 1119.505,1668.347 ccw(c1119.931,1667.92) v1@1119.328,1667.92 ; v1@1119.328,1667.92 ccw(c1118.724,1667.92) 1119.151,1668.347 cw(c1118.724,1667.92) v1@1119.328,1667.92
  BottomLayer w0.5: v2(1117.405,1672.322) 1119.328,1670.324 v1(1119.328,1667.824)
NetC526_1: C526.1 UT5.2 | length 6.8
  TopLayer w0.2: C526.1@1107.328,1673.224 1107.461,1673.224 1110.161,1670.524 UT5.2@1110.928,1670.524 ; C526.1@1107.378,1672.824 cw(c1107.378,1671.658) 1108.202,1672.483 ; C526.1@1107.378,1673.024 cw(c1107.378,1672.341) C526.1@1107.861,1672.824 ; C526.1@1107.778,1673.224 ccw(c1108.544,1673.224) 1108.002,1672.683
NetCT62_1: CT62.1 UT6.3 | length 7.1
  TopLayer w0.5: CT62.1@1063.506,1659.808 1063.61,1659.912 UT6.3@1068.095,1659.912 ; CT62.1@1063.958,1659.357 cw(c1065.299,1658.016) 1065.299,1659.912 ; CT62.1@1063.958,1660.26 ccw(c1064.799,1661.101) 1064.799,1659.912
NetCT62_2: CT61.2 CT62.2 RT62.1 | length 16.8
  TopLayer w0.2: CT62.2@1060.006,1660.479 CT62.2@1060.139,1660.611
  TopLayer w0.5: RT62.1@1057.31,1660.611 CT62.2@1060.139,1660.611 ; RT62.1@1057.445,1660.611 cw(c1057.445,1657.628) CT62.2@1059.554,1659.738 ; RT62.1@1057.537,1660.435 cw(c1057.964,1660.008) 1057.964,1660.611 cw(c1057.964,1661.215) RT62.1@1057.537,1660.788 ; 1058.652,1660.611 cw(c1058.652,1658.835) CT62.2@1059.908,1660.091 ; CT61.2@1059.554,1656.741 ccw(c1058.463,1657.832) 1060.006,1657.832 ccw(c1061.549,1657.832) CT61.2@1060.458,1656.741 ; CT62.2@1059.554,1658.976 cw(c1058.463,1657.885) 1060.006,1657.885 cw(c1061.549,1657.885) CT62.2@1060.458,1658.976 ; CT61.2@1060.006,1656.208 CT62.2@1060.006,1660.479
NetCT63_2: CT63.2 RT64.2 RT65.1 | length 12.9
  TopLayer w0.2: CT63.2@1070.272,1655.223 cw(c1070.955,1654.54) 1070.955,1655.506 cw(c1070.955,1656.471) CT63.2@1070.272,1655.789 ; CT63.2@1070.379,1655.506 ccw(c1070.379,1657.071) RT64.2@1071.559,1656.043 ; 1070.819,1655.506 ccw(c1070.819,1656.688) RT64.2@1071.71,1655.911 ; RT64.2@1071.258,1655.506 ccw(c1071.258,1656.305) RT64.2@1071.861,1655.78 ; RT64.2@1071.408,1656.174 cw(c1069.94,1657.454) CT63.2@1069.94,1655.506 RT64.2@1071.654,1655.506 ; RT65.1@1071.522,1654.795 ccw(c1071.037,1655.37) 1071.79,1655.37 ; RT64.2@1071.527,1655.629 cw(c1070.893,1654.994) 1071.79,1654.994 ; RT64.2@1071.674,1655.535 cw(c1071.614,1655.37) 1071.79,1655.37 ; RT65.1@1071.79,1654.089 1071.79,1655.37 ; RT65.1@1071.79,1654.897 cw(c1072.824,1654.897) RT64.2@1072.093,1655.629 ; 1071.79,1655.38 cw(c1072.341,1655.38) RT64.2@1071.951,1655.77 ; RT64.2@1071.91,1655.524 ccw(c1071.949,1655.37) 1071.79,1655.37 ; RT65.1@1072.049,1654.785 cw(c1072.581,1655.37) 1071.79,1655.37
NetCU10_2: CU10.2 UU1.2 X2.2 | length 21.6
  TopLayer w0.2: UU1.2@1067.315,1676 1067.315,1674.93 1067.948,1674.297 1069.838,1674.297 1070.885,1673.25 1071.85,1673.25 1072.7,1674.1 ; X2.2@1072.388,1674.62 cw(c1072.111,1674.1) 1072.7,1674.1 ; X2.2@1072.482,1674.796 cw(c1072.289,1674.434) 1072.7,1674.434 cw(c1073.111,1674.434) X2.2@1072.918,1674.796 ; X2.2@1073.012,1674.62 ccw(c1073.289,1674.1) 1072.7,1674.1 ; X2.2@1073.027,1674.877 cw(c1073.815,1674.088) 1073.815,1675.204 cw(c1073.815,1676.319) X2.2@1073.027,1675.53 ; X2.2@1073.168,1674.736 cw(c1074.298,1673.606) 1074.298,1675.204 cw(c1074.298,1676.802) X2.2@1073.168,1675.672 ; 1074.64,1675.204 ccw(c1074.64,1677.01) CU10.2@1075.917,1675.733 ; 1075.123,1675.204 ccw(c1075.123,1676.527) CU10.2@1076.059,1675.591 ; 1075.606,1675.204 ccw(c1075.606,1676.044) CU10.2@1076.2,1675.45 ; CU10.2@1076.1,1675.1 1075.996,1675.204 X2.2@1072.7,1675.204 1072.7,1674.1
NetCU11_2: CU11.2 UU1.3 X2.1 | length 24.2
  TopLayer w0.2: UU1.3@1066.68,1676 1066.68,1674.75 1067.633,1673.797 1069.698,1673.797 1070.695,1672.8 1071.9,1672.8 1072.7,1672 X2.1@1072.7,1670.4 ; X2.1@1072.232,1670.668 ccw(c1071.102,1671.798) 1072.7,1671.798 ccw(c1074.298,1671.798) 1073.168,1670.668 ccw(c1074.298,1671.798) 1074.298,1670.2 ccw(c1074.298,1668.602) X2.1@1073.168,1669.732 ; X2.1@1072.373,1670.527 ccw(c1071.585,1671.315) 1072.7,1671.315 ccw(c1073.815,1671.315) 1073.027,1670.527 ccw(c1073.815,1671.315) 1073.815,1670.2 ccw(c1073.815,1669.085) X2.1@1073.027,1669.873 ; X2.1@1072.7,1670.2 CU11.2@1076,1670.2 ; 1074.798,1670.2 cw(c1074.798,1668.615) CU11.2@1075.919,1669.736 ; 1075.281,1670.2 cw(c1075.281,1669.098) CU11.2@1076.06,1669.877 ; 1075.674,1670.2 ccw(c1075.674,1670.546) CU11.2@1075.919,1670.301
NetD2_2: D2.2 RH16.1 | length 10
  TopLayer w0.2: RH16.1@1067.633,1649.417 cw(c1068.316,1648.734) 1068.316,1649.7 cw(c1068.316,1650.666) RH16.1@1067.633,1649.983 ; RH16.1@1067.729,1649.7 ccw(c1067.729,1651.626) D2.2@1069.205,1650.389 ; 1068.157,1649.7 ccw(c1068.157,1651.267) D2.2@1069.358,1650.261 ; 1068.586,1649.7 ccw(c1068.586,1650.908) D2.2@1069.512,1650.132 ; D2.2@1069.052,1650.518 cw(c1067.3,1651.985) RH16.1@1067.3,1649.7 D2.2@1069.7,1649.7
NetD4_2: D3.2 D4.2 R71.1 | length 10.2
  TopLayer w0.5: R71.1@1170.6,1624.5 1170.7,1624.6 D3.2@1172.4,1624.6 ; R71.1@1170.777,1624.373 cw(c1171.324,1623.826) 1171.324,1624.6 ; 1171.172,1624.6 ccw(c1171.172,1625.978) D3.2@1172.146,1625.004 ; 1171.414,1624.6 cw(c1171.414,1623.564) 1172.146,1624.296 cw(c1171.293,1623.443) 1172.5,1623.443 ; D4.2@1172.146,1622.804 ccw(c1171.293,1623.657) 1172.5,1623.657 ccw(c1173.707,1623.657) D4.2@1172.854,1622.804 ; D4.2@1172.5,1622.8 D3.2@1172.5,1624.9 ; 1172.5,1623.443 cw(c1173.707,1623.443) D3.2@1172.854,1624.296
NetDC_IN_1: DC_IN.1 FUSE.1
NetFUSE2_1: FUSE2.1 USB1_2.1 USB1_2.5 | length 10.9
  TopLayer w1: FUSE2.1@1049.6,1682.4 v1(1051.3,1682.4) ; FUSE2.1@1049.685,1682.015 cw(c1050.615,1681.085) 1050.615,1682.4
  BottomLayer w1: v1@1051.3,1682.5 1054,1685.2 USB1_2.1@1054,1689.5
NetFUSE3_1: FUSE3.1 USB3_4.1 USB3_4.5 | length 8.4
  TopLayer w1: USB3_4.1@1074.766,1689.576 1074.766,1685.477 FUSE3.1@1077.798,1682.445
NetFUSE_2: C101.1 C102.1 D101.2 FUSE.2 S1.1 | length 13.9
  TopLayer w2: 1207.073,1669.927 C101.1@1207.073,1675.185 ; 1207.169,1669.927 1211.3,1665.796 ; 1211.204,1665.796 S1.1@1214.008,1665.796
NetIrDA1_1: IrDA1.1 RA2.1 | length 6.2
  TopLayer w0.2: RA2.1@1063.467,1591.217 cw(c1062.664,1590.414) 1063.8,1590.414 ; IrDA1.1@1063.512,1589.442 ccw(c1062.815,1590.139) 1063.8,1590.139 ccw(c1064.785,1590.139) IrDA1.1@1064.089,1589.442 ; RA2.1@1063.609,1591.359 cw(c1063.146,1590.896) 1063.8,1590.896 ; RA2.1@1063.7,1591.5 1063.8,1591.4 IrDA1.1@1063.8,1588.9 ; 1063.8,1590.655 cw(c1064.595,1590.655) RA2.1@1064.033,1591.217
NetJ3_2: BUZZER.1 J3.2 | length 21.7
  TopLayer w0.5: BUZZER.1@1085.2,1588.4 1090.7,1582.9 1090.7,1574.7 J3.2@1092.2,1573.2 ; BUZZER.1@1085.454,1587.888 cw(c1085.454,1587.265) BUZZER.1@1085.894,1587.706 ; BUZZER.1@1085.966,1588.4 ccw(c1087.815,1588.4) 1086.508,1587.092 ; 1091.09,1574.31 ccw(c1092.2,1575.419) J3.2@1092.2,1573.85 ; 1091.573,1573.827 cw(c1091.146,1573.4) J3.2@1091.75,1573.4
NetL503_1: C506.2 L503.1 UT5.32 | length 14
  TopLayer w0.2: L503.1@1112,1678.45 ccw(c1112,1679.295) 1112.597,1678.697 ; L503.1@1112.1,1678.2 C506.2@1113.5,1679.6 ; L503.1@1112.2,1678.05 cw(c1112.804,1678.05) L503.1@1112.377,1678.477 ; L503.1@1112.4,1678.05 cw(c1113.486,1678.05) 1112.718,1678.818 ; 1112.746,1678.846 ccw(c1111.893,1679.7) C506.2@1113.1,1679.7 ; 1112.988,1679.088 cw(c1113.5,1678.576) C506.2@1113.5,1679.3 ; 1113.088,1679.188 ccw(c1112.576,1679.7) C506.2@1113.3,1679.7
  TopLayer w0.5: v2(1110.8,1672.3) 1111.2,1672.3 1111.5,1672 ; L503.1@1111.823,1677.773 cw(c1111.396,1677.346) 1112,1677.346 cw(c1112.604,1677.346) L503.1@1112.177,1677.773 ; v1(1112,1675.6) L503.1@1112,1678
  BottomLayer w0.5: v2(1110.8,1672.3) 1110.8,1674.4 v1(1112,1675.6)
NetLED1_2: LED1.2 R9.2 | length 5.5
  TopLayer w0.2: LED1.2@1187.991,1573.041 1188.741,1573.791 ; LED1.2@1188.076,1573.431 ccw(c1188.186,1573.853) LED1.2@1188.494,1573.544 ; LED1.2@1188.126,1573.624 ccw(c1188.288,1574.245) 1188.741,1573.791 ; R9.2@1188.459,1574.659 cw(c1187.776,1573.976) 1188.741,1573.976 cw(c1189.707,1573.976) R9.2@1189.024,1574.659 ; LED1.2@1188.523,1573.167 cw(c1189.28,1573.252) 1188.741,1573.791 ; R9.2@1188.741,1574.941 1188.741,1573.791
NetLED2_2: LED2.2 R10.2 | length 5.9
  TopLayer w0.2: LED2.2@1193.3,1572.95 1194.25,1573.9 ; LED2.2@1193.386,1573.489 ccw(c1193.552,1574.108) 1194.005,1573.655 ; LED2.2@1193.438,1573.682 ccw(c1193.655,1574.495) 1194.25,1573.9 ; LED2.2@1193.835,1573.165 cw(c1194.608,1573.165) 1194.061,1573.711 ; R10.2@1193.97,1574.564 cw(c1193.322,1573.9) 1194.25,1573.9 ; R10.2@1194.25,1574.85 1194.25,1573.9 ; R10.2@1194.53,1574.564 ccw(c1195.178,1573.9) 1194.25,1573.9
NetPOWER_1: POWER.1 R331.2 | length 7.1
  TopLayer w0.2: R331.2@1205.248,1658.505 1207.492,1658.505 POWER.1@1207.498,1658.5 ; R331.2@1205.581,1658.222 cw(c1206.264,1657.54) 1206.264,1658.505 cw(c1206.264,1659.471) R331.2@1205.581,1658.788 ; 1206.127,1658.505 cw(c1206.127,1657.194) POWER.1@1207.055,1658.121 ; 1206.156,1658.505 ccw(c1206.156,1659.777) POWER.1@1207.055,1658.878 ; 1206.61,1658.505 cw(c1206.61,1657.677) POWER.1@1207.196,1658.263 ; 1206.638,1658.505 ccw(c1206.638,1659.294) POWER.1@1207.196,1658.736
NetPR_2: PR.2 RA1.2 | length 7.8
  TopLayer w0.4: PR.2@1058.4,1589.1 1060.3,1589.1 1061.35,1588.05 RA1.2@1061.35,1587 ; PR.2@1058.824,1588.676 cw(c1059.849,1587.651) 1059.849,1589.1 cw(c1059.849,1590.549) PR.2@1058.824,1589.524 ; RA1.2@1061.138,1587.212 ccw(c1060.626,1587.724) 1061.35,1587.724 ccw(c1062.074,1587.724) RA1.2@1061.562,1587.212
NetQ1_B: Q1.B R17.2 | length 5.1
  TopLayer w0.2: R17.2@1188.459,1580.059 cw(c1187.739,1579.339) 1188.757,1579.339 ; Q1.B@1188.468,1579.116 ccw(c1187.772,1579.812) 1188.757,1579.812 ccw(c1189.742,1579.812) Q1.B@1189.045,1579.116 ; R17.2@1188.6,1580.2 cw(c1188.222,1579.822) 1188.757,1579.822 ; R17.2@1188.741,1580.341 1188.757,1580.326 Q1.B@1188.757,1578.7 ; 1188.757,1579.412 cw(c1189.67,1579.412) R17.2@1189.024,1580.059
NetQ1_C: Q1.C R9.1 | length 5.1
  TopLayer w0.2: R9.1@1186.751,1575.261 ccw(c1186.391,1575.741) 1186.991,1575.741 ; 1186.928,1575.678 cw(c1187.724,1574.881) Q1.C@1187.774,1576.007 ; R9.1@1186.991,1574.941 1186.991,1575.741 ; 1187.185,1575.935 ccw(c1186.705,1576.414) Q1.C@1187.383,1576.414 ; R9.1@1187.231,1575.261 cw(c1187.591,1575.741) 1186.991,1575.741 ; 1187.249,1575.999 cw(c1187.751,1575.497) Q1.C@1187.782,1576.207 ; Q1.C@1187.791,1576.541 1186.991,1575.741
NetQ2_C: Q2.C R10.1 | length 5.1
  TopLayer w0.2: R10.1@1192.26,1575.17 ccw(c1191.9,1575.65) 1192.5,1575.65 ; 1192.437,1575.587 cw(c1193.233,1574.79) Q2.C@1193.282,1575.915 ; R10.1@1192.5,1574.85 1192.5,1575.65 ; 1192.693,1575.843 ccw(c1192.214,1576.323) Q2.C@1192.892,1576.323 ; R10.1@1192.74,1575.17 cw(c1193.1,1575.65) 1192.5,1575.65 ; 1192.758,1575.908 cw(c1193.26,1575.406) Q2.C@1193.291,1576.115 ; Q2.C@1193.3,1576.45 1192.5,1575.65
NetQ10_B: Q10.B RF1.1 RF2.1 | length 10.4
  TopLayer w0.2: Q10.B@1087.859,1599.435 1090.835,1599.435 RF1.1@1090.9,1599.5 ; Q10.B@1088.274,1599.146 cw(c1088.971,1598.45) 1088.971,1599.435 cw(c1088.971,1600.42) Q10.B@1088.274,1599.723 ; 1088.597,1599.435 ccw(c1088.597,1600.446) RF2.1@1089.312,1599.731 ; 1088.661,1599.435 cw(c1088.661,1598.515) RF2.1@1089.312,1599.165 ; 1089.079,1599.435 ccw(c1089.079,1599.963) RF2.1@1089.453,1599.59 ; RF2.1@1089.736,1599.59 ccw(c1090.11,1599.963) 1090.11,1599.435 ; RF2.1@1089.877,1599.165 cw(c1090.528,1598.515) RF1.1@1090.528,1599.435 ; RF2.1@1089.877,1599.731 ccw(c1090.593,1600.446) RF1.1@1090.593,1599.435 ; RF2.1@1089.997,1599.435 ccw(c1089.997,1600.446) RF1.1@1090.712,1599.731 ; RF2.1@1090.061,1599.435 cw(c1090.061,1598.515) RF1.1@1090.712,1599.165 ; 1090.479,1599.435 ccw(c1090.479,1599.963) RF1.1@1090.853,1599.59
NetQ10_C: BUZZER.2 Q10.C | length 7.4
  TopLayer w0.2: Q10.C@1085.4,1600.1 Q10.C@1085.7,1600.4
  TopLayer w0.5: BUZZER.2@1085.092,1596.382 ccw(c1084.348,1597.126) 1085.4,1597.126 ; BUZZER.2@1085.4,1596 Q10.C@1085.4,1600.1 ; 1085.4,1597.386 ccw(c1086.82,1597.386) BUZZER.2@1085.816,1596.382 ; 1085.4,1599.359 cw(c1086.614,1599.359) Q10.C@1085.755,1600.218
NetQH1_B: QH1.B RH12.1 RH13.2 | length 10.3
  TopLayer w0.2: RH13.2@1063.715,1651.688 ccw(c1063.024,1652.38) 1064.002,1652.38 ; RH12.1@1063.719,1652.712 cw(c1063.036,1652.029) 1064.002,1652.029 cw(c1064.967,1652.029) RH12.1@1064.285,1652.712 ; 1064.002,1652.362 ccw(c1064.955,1652.362) RH13.2@1064.281,1651.688 ; RH13.2@1064.048,1651.405 1064.002,1651.452 RH12.1@1064.002,1652.995 1065.605,1652.995 QH1.B@1065.7,1652.9 ; RH12.1@1064.148,1652.995 ccw(c1064.148,1654.519) QH1.B@1065.226,1653.441 ; RH12.1@1064.335,1652.712 cw(c1065.017,1652.029) 1065.017,1652.995 cw(c1065.017,1653.96) RH12.1@1064.335,1653.277 ; 1064.631,1652.995 ccw(c1064.631,1654.036) QH1.B@1065.367,1653.3 ; 1064.911,1652.995 cw(c1064.911,1652.549) QH1.B@1065.226,1652.864
NetR18_2: Q2.B R18.2 | length 5.1
  TopLayer w0.2: R18.2@1193.967,1579.967 cw(c1193.248,1579.248) 1194.265,1579.248 ; Q2.B@1193.977,1579.024 ccw(c1193.28,1579.721) 1194.265,1579.721 ccw(c1195.25,1579.721) Q2.B@1194.554,1579.024 ; R18.2@1194.109,1580.109 cw(c1193.73,1579.73) 1194.265,1579.73 ; R18.2@1194.25,1580.25 1194.265,1580.235 Q2.B@1194.265,1578.609 ; 1194.265,1579.321 cw(c1195.179,1579.321) R18.2@1194.533,1579.967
